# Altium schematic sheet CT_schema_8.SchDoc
size 274 x 160 mm
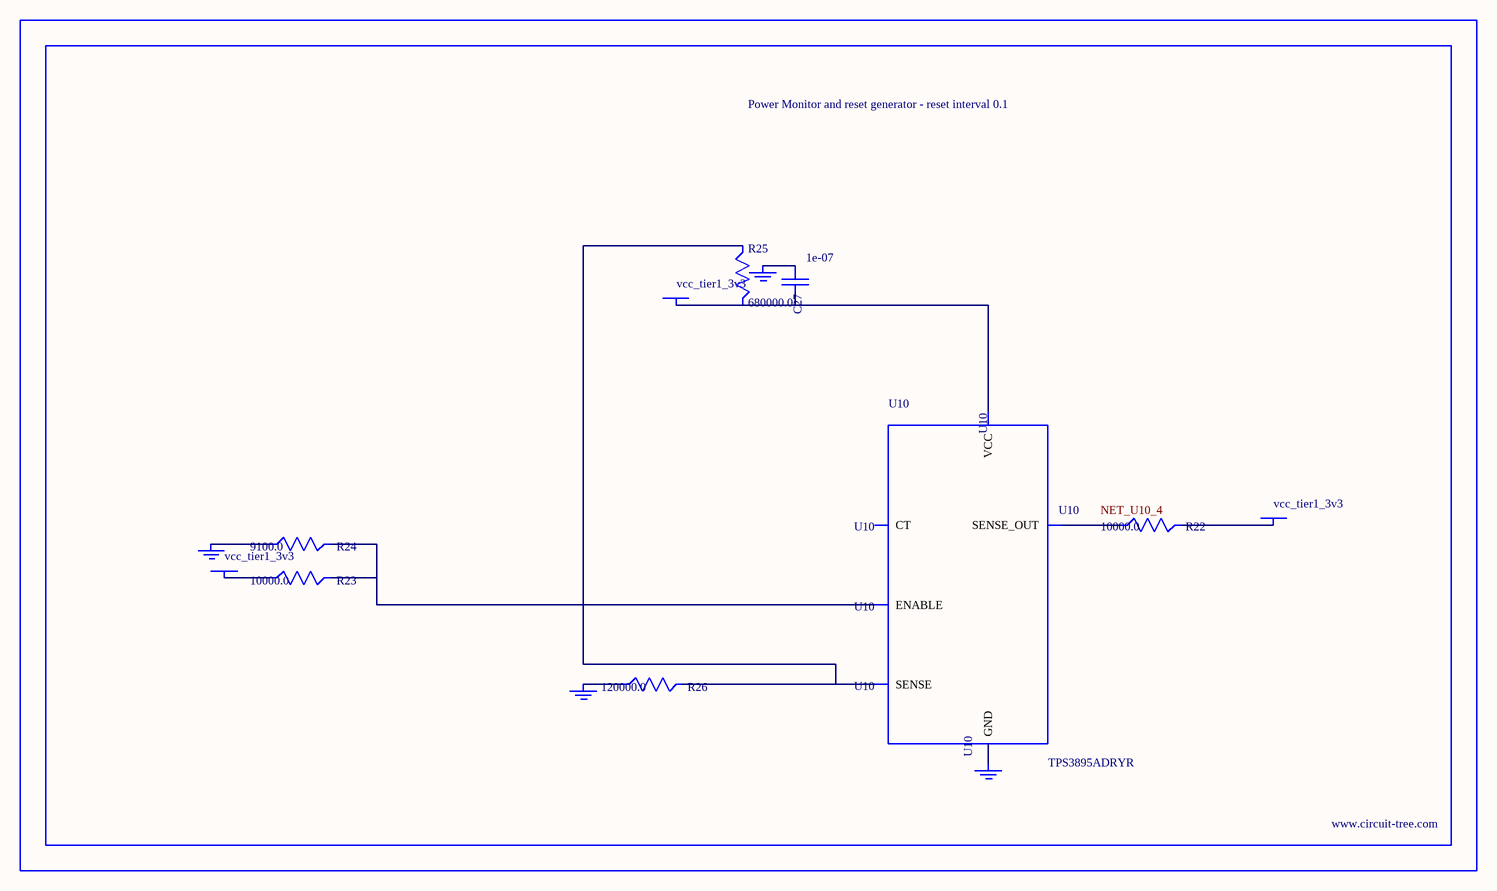
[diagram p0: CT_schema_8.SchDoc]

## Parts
BORDER7  (no value)
C27  1e-07  [C0402]
GND_INSTANCE_7_0  (no value)
GND_INSTANCE_7_1  (no value)
GND_INSTANCE_7_2  (no value)
GND_INSTANCE_7_3  (no value)
POWER_INSTANCE_7_0  vcc_tier1_3v3
POWER_INSTANCE_7_1  vcc_tier1_3v3
POWER_INSTANCE_7_2  vcc_tier1_3v3
R22  10000.0  [R0603]
R23  10000.0  [R0603]
R24  9100.0  [R0603]
R25  680000.0  [R0603]
R26  120000.0  [R0603]
U10  TPS3895ADRYR  [SON-6]

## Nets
NetC27_1: C27.1 GND_INSTANCE_7_2.0(GND)
NetC27_2: C27.2 POWER_INSTANCE_7_2.0(PWR) R25.2 U10.6(VCC)
NetGND_INSTANCE_7_0_0: GND_INSTANCE_7_0.0(GND) R24.1
NetGND_INSTANCE_7_1_0: GND_INSTANCE_7_1.0(GND) R26.1
NetGND_INSTANCE_7_3_0: GND_INSTANCE_7_3.0(GND) U10.2(GND)
NetPOWER_INSTANCE_7_0_0: POWER_INSTANCE_7_0.0(PWR) R23.1
NetPOWER_INSTANCE_7_1_0: POWER_INSTANCE_7_1.0(PWR) R22.2
NetR22_1: R22.1 U10.4(SENSE_OUT)
NetR23_2: R23.2 R24.2 U10.1(ENABLE)
NetR25_1: R25.1 R26.2 U10.3(SENSE)

Not connected (* = marked no-connect by the designer): U10 5(CT)

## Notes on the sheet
- Labels drawn without touching a wire or pin: NET_U10_4

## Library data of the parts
BORDER7 = BORDER_PAGE7
C27 = C0402C104K3RACTU
GND_INSTANCE_7_0-GND_INSTANCE_7_3 = GND
POWER_INSTANCE_7_0-POWER_INSTANCE_7_2 = PWR
R22 R23 = RC0603JR-0710KL
R24 = RC0603JR-079K1L
R25 = RC0603JR-07680KL
R26 = RC0603JR-07120KL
